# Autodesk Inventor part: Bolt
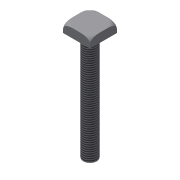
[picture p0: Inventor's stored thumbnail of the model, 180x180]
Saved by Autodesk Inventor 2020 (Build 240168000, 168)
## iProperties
Created: 2009-04
Part Number: Bolt
Document SubType Name: Modeling
Designer: Sham
Density: 1 g/cm^3
Material: Generic
Appearance: Default
Author: Sham
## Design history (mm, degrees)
sketch "Sketch1"
  geometry: L1 (-12, 12)-(12, 12); L2 (12, 12)-(12, -12); L3 (12, -12)-(-12, -12); L4 (-12, -12)-(-12, 12); 1 further point
  constraints: 8 end point, 2 parallel, 2 perpendicular, 1 horizontal, 1 other
  dimensions: "d0" = 24 distance of L1.start L1.end; "d1" = 12 distance from line of L2 point (0, 0); "d2" = 12 distance from line of L1 point (0, 0)
extrude "Extrusion1" new body sketch "Sketch1" distance "d3" = 8; taper "d4" = 0 deg
sketch "Sketch2"
  geometry: C1 r 6 at (0, 0)
  constraints: 1 centre point
  dimensions: "d5" = 12 diameter of C1
extrude "Extrusion2" join sketch "Sketch2" distance "d6" = 96; taper "d7" = 0 deg
workpoint "Work Point1"
workplane "Work Plane1"
sketch "Sketch3"
  geometry: L1 (33.941, 5)-(33.941, 6); L2 (28.941, 0)-(28.405, 0); L3 (16.971, 125.007)-(16.971, -22.043) reference; A1 r 5 centre (28.941, 5) between (28.941, 0) and (33.941, 5); 1 further point
  constraints: 4 end point, 2 point on circle, 2 point on line, 2 tangent, 1 centre point, 1 perpendicular
  dimensions: "d10" = 5 radius of A1
revolve "Revolution1" sketch "Sketch3" stored, may be unused: angle "d12" = 90 deg
thread "Thread1" dims "d13" = 96, "d14" = 0
body "Solid1"
other parameters: "d11" = 90 deg
